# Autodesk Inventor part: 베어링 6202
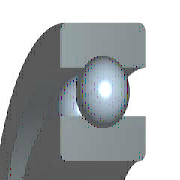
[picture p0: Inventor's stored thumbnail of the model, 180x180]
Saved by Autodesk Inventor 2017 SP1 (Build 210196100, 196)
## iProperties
IsCustomPart: 1
Created: 2015-12
Part Number: 베어링 6202
Material: 강철, 연강
Description: 깊은 그루브 볼 베어링
Document SubType Name: Modeling
Standard: KS B 2023
Designer: mdu
Standards Organization: KS
Language: ko-KR
Size Designation: 6202 - 15 x 35 x 11
Categories: <MemberInstance><Categories><Category DisplayName="샤프트 부품" InternalName="7f7aeb1f-a693-4053-b835-cee3144e0d98" Mnemonic="SHFT"><Category DisplayName="베어링" Inter
Density: 7.86 g/cm^3
Mass: 45.8725 g
Surface Area: 51.5584 cm^2
Volume: 5.83619 cm^3
Appearance: 노란색
Author: mdu
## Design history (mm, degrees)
sketch "스케치" dims "d0" = 5.2 (= -0.26 x WD + 0.26 x BD)
  geometry: L1 (2.9, 12.5)-(8.1, 12.5); L2 (5.5, 12.5)-(5.5, 9.9); L3 (5.5, 12.5)-(5.5, 15.1); L4 (3.568, 10.76)-(0, 10.76); L5 (0, 7.5)-(11, 7.5); L6 (3.568, 14.24)-(0, 14.24); L7 (0, 17.5)-(11, 17.5); L8 (11, 7.5)-(11, 10.76); L9 (7.432, 10.76)-(11, 10.76); L10 (7.432, 14.24)-(11, 14.24); L11 (11, 17.5)-(11, 14.24); L12 (-1.4, 0)-(8.4, 0) reference; L13 (0, -0.3)-(0, 5.3) reference
  constraints: 22 end point, 4 point on line, 2 collinear, 2 perpendicular, 2 symmetric about line, 1 midpoint, 1 parallel, 14 other
  dimensions: "d9" = 15 diameter of L5 L12 (= WD); "d11" = 35 diameter of L7 L12 (= BD); "d12" = 11 distance between parallel lines of L8 L13 (= KB); "d13" = 21.52 diameter of L9 L12 (= 0.326 x BD + 0.674 x WD)
revolve "본체" stored, may be unused: angle "d6" = 90 deg
revolve "볼" stored, may be unused: angle "d7" = 90 deg
pattern_circular "IDS_ARRAYBALL[SIMPL:T]" dims angle "d3" = 360 deg
body "Solid1"
fillet "모깎기1" dims "d1" = 0.6 (= KRS)
other parameters: "WD" = 15 [user parameter; used in 5 equation terms], "BD" = 35 [user parameter; used in 5 equation terms], "KB" = 11 [user parameter; used in 1 equation term], "KRS" = 0.6 [user parameter; used in 1 equation term], "d4" = 0, "d5" = 0, "d8" = 0, "d14" = 0, "d15" = 0, "BBA" = 0 [user parameter], "BC0" = 3750000 [user parameter], "BC" = 7800000 [user parameter], "BR" = 17.5 (= 0.5 x BD) [user parameter], "WR" = 7.5 (= 0.5 x WD) [user parameter]
